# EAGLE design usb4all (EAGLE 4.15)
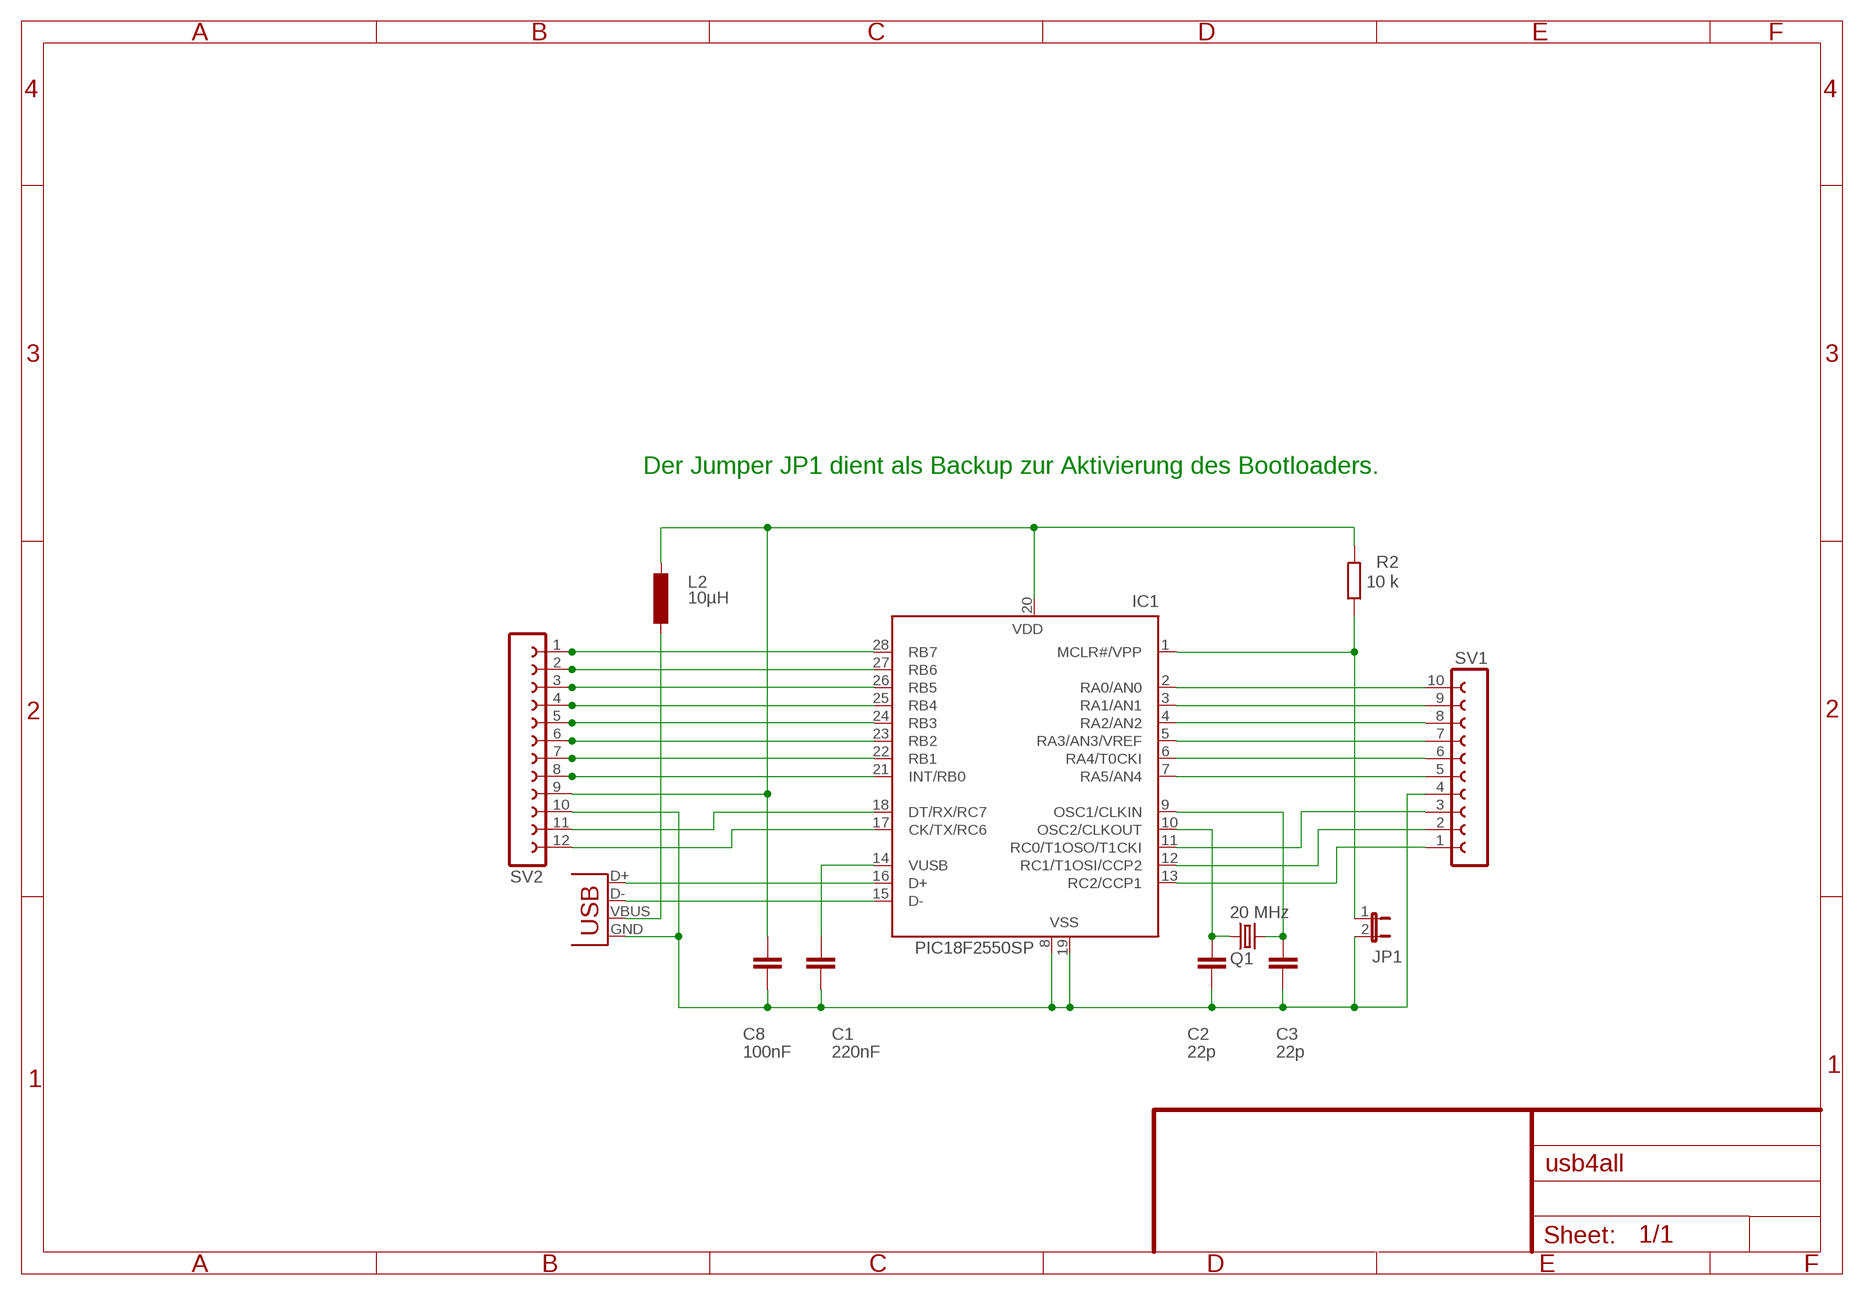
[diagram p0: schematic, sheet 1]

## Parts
C1  220nF  C-EU050-025X075  [C050-025X075]
C2  22p  C-EU025-025X050  [C025-025X050]
C3  22p  C-EU025-025X050  [C025-025X050]
C8  100nF  C-EU050-025X075  [C050-025X075]
IC1  PIC18F2550SP  PIC18F2455SP  [DIL28-3]
JP1  JP1E  [JP1]
L2  10µH  L-EU0207/10  [0207/10]
Q1  20 MHz  CRYTALHC18U-V  [HC18U-V]
R2  10 k  R-EU_0207/10  [0207/10]
SV1  FE10-1  [FE10]
SV2  FE12-1  [FE12]
X2  USB-B-H  [USB-B-H]

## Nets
+5V: C8.1 IC1.20(VDD) L2.2 R2.2 SV2.9
GND: C1.2 C2.2 C3.2 C8.2 IC1.8(VSS) IC1.19(VSS) JP1.2 SV1.4 SV2.10 X2.GND
N$1: IC1.15(D-) X2.D-
N$2: IC1.16(D+) X2.D+
N$3: L2.1 X2.VBUS
N$4: IC1.28(RB7) SV2.1
N$5: C1.1 IC1.14(VUSB)
N$6: C2.1 IC1.10(OSC2/CLKOUT) Q1.1
N$7: C3.1 IC1.9(OSC1/CLKIN) Q1.2
N$8: IC1.1(MCLR#/VPP) JP1.1 R2.1
N$9: IC1.27(RB6) SV2.2
N$10: IC1.26(RB5) SV2.3
N$11: IC1.2(RA0/AN0) SV1.10
N$12: IC1.25(RB4) SV2.4
N$13: IC1.24(RB3) SV2.5
N$14: IC1.23(RB2) SV2.6
N$15: IC1.22(RB1) SV2.7
N$16: IC1.21(INT/RB0) SV2.8
N$17: IC1.18(DT/RX/RC7) SV2.11
N$18: IC1.17(CK/TX/RC6) SV2.12
N$19: IC1.7(RA5/AN4) SV1.5
N$20: IC1.3(RA1/AN1) SV1.9
N$21: IC1.4(RA2/AN2) SV1.8
N$22: IC1.5(RA3/AN3/VREF) SV1.7
N$23: IC1.6(RA4/T0CKI) SV1.6
N$24: IC1.12(RC1/T1OSI/CCP2) SV1.2
N$25: IC1.11(RC0/T1OSO/T1CKI) SV1.3
N$26: IC1.13(RC2/CCP1) SV1.1

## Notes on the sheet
- Der Jumper JP1 dient als Backup zur Aktivierung des Bootloaders.

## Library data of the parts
C1-C3 C8 = rcl:C-EU: CAPACITOR, European symbol
IC1 = sprut:PIC18F2455: FLASH based microcontroler USB 2.0 24K /ROM- 2048 Bytes RAM
JP1 = jumper:JP1E: JUMPER
L2 = rcl:L-EU: INDUCTOR, European symbol
Q1 = crystal:CRYTAL: CRYSTAL
R2 = rcl:R-EU_: RESISTOR, European symbol
SV1 = con-lsta:FE10-1: FEMALE HEADER
SV2 = con-lsta:FE12-1: FEMALE HEADER
X2 = con-usb:USB: USB Connectors

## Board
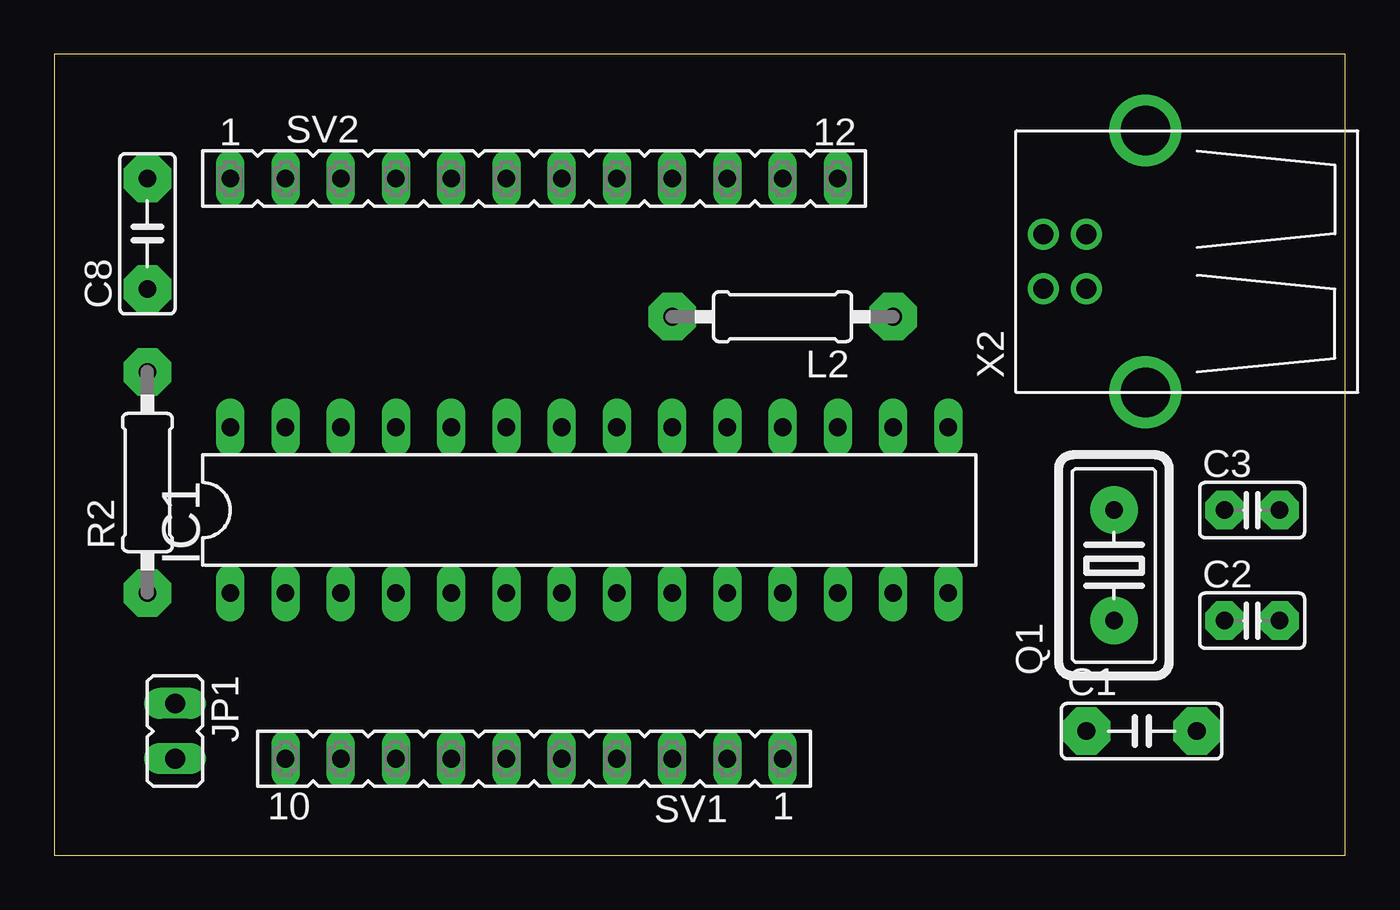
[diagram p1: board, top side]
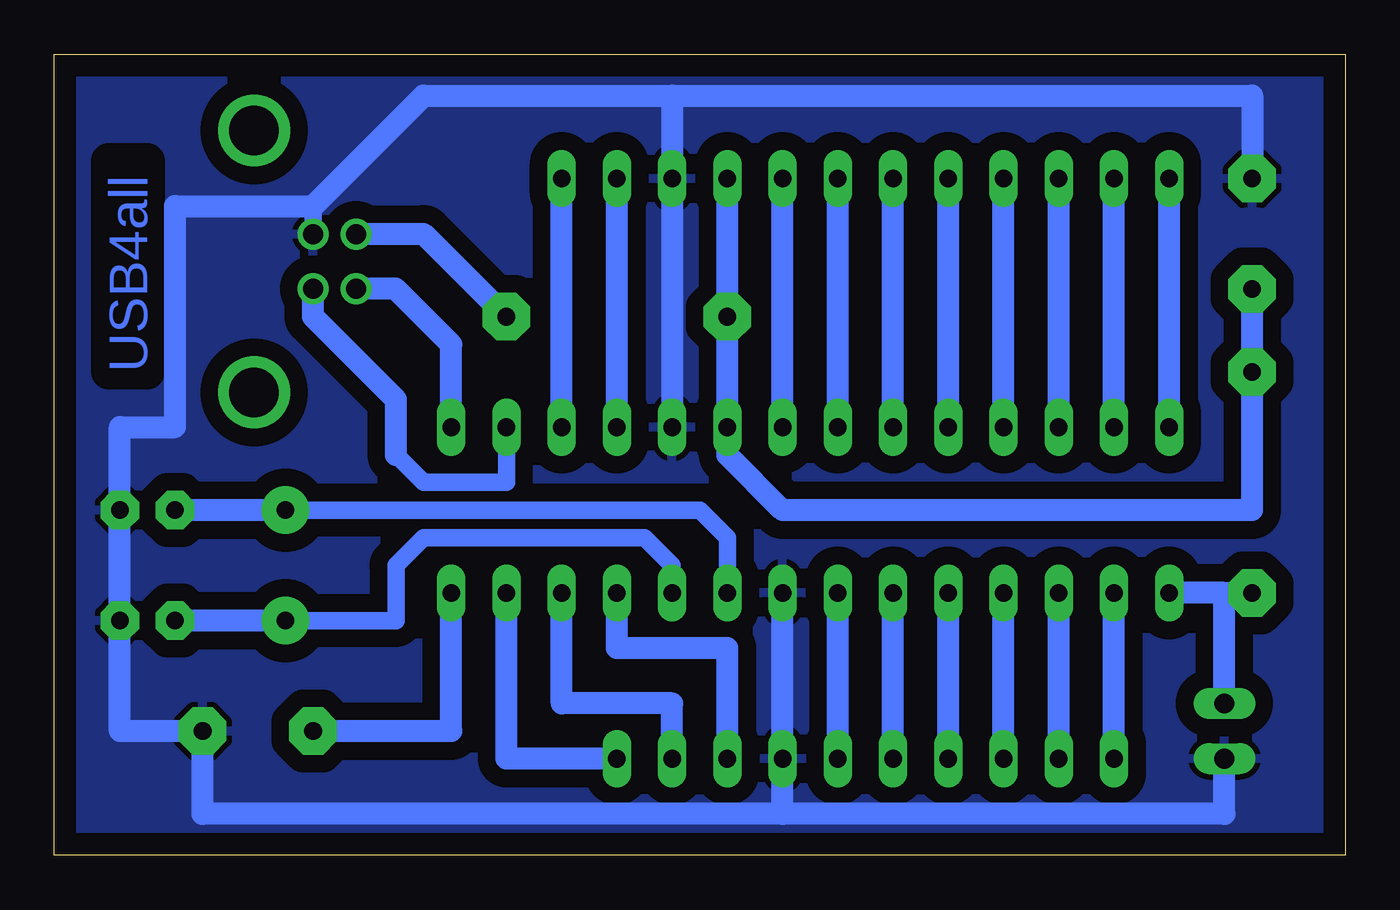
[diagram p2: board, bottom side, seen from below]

Size 59.36 x 36.82 mm. Coordinates in mm from the lower left corner, seen from the top.
Outline: 0,0 59.36,0 59.36,36.82 0,36.82 0,0
Copper layers (1*16): Top 0.035mm / dielectric 1.5mm / Bottom 0.035mm
Design rules "default": minimum track width 10mil, minimum drill 24mil, track to track 8mil, track to pad 8mil, pad to pad 8mil, via to via 8mil, smd to smd 8mil, copper to edge 40mil, drill to drill 8mil, minimum pad ring 10mil, minimum via ring 8mil, stop-mask expansion 4mil, vias tented up to drill 0mil, thermal gap 10mil

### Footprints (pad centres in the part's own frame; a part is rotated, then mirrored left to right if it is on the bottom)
C050-025X075 = drill 0.813 pad 2.184 octagon: 1 -2.54,0; 2 2.54,0
C025-025X050 = drill 0.813 pad 1.778 octagon: 1 -1.27,0; 2 1.27,0
DIL28-3 = drill 0.813 long: 1 -16.51,-3.81; 2 -13.97,-3.81; 3 -11.43,-3.81; 4 -8.89,-3.81; 5 -6.35,-3.81; 6 -3.81,-3.81; 7 -1.27,-3.81; 8 1.27,-3.81; 9 3.81,-3.81; 10 6.35,-3.81; 11 8.89,-3.81; 12 11.43,-3.81; 13 13.97,-3.81; 14 16.51,-3.81; 15 16.51,3.81; 16 13.97,3.81; 17 11.43,3.81; 18 8.89,3.81; 19 6.35,3.81; 20 3.81,3.81; 21 1.27,3.81; 22 -1.27,3.81; 23 -3.81,3.81; 24 -6.35,3.81; 25 -8.89,3.81; 26 -11.43,3.81; 27 -13.97,3.81; 28 -16.51,3.81
JP1 = drill 0.914 long: 1 0,-1.27; 2 0,1.27
0207/10 = drill 0.813 pad 2.184 octagon: 1 -5.08,0; 2 5.08,0
HC18U-V = drill 0.813 pad 2.184 round: 1 -2.54,0; 2 2.54,0
FE10 = drill 0.813 long: 1 -11.43,0; 2 -8.89,0; 3 -6.35,0; 4 -3.81,0; 5 -1.27,0; 6 1.27,0; 7 3.81,0; 8 6.35,0; 9 8.89,0; 10 11.43,0
FE12 = drill 0.813 long: 1 -13.97,0; 2 -11.43,0; 3 -8.89,0; 4 -6.35,0; 5 -3.81,0; 6 -1.27,0; 7 1.27,0; 8 3.81,0; 9 6.35,0; 10 8.89,0; 11 11.43,0; 12 13.97,0
USB-B-H = drill 0.914 round: D+ 0,1.25; D- 1.981,1.25; GND 0,-1.25; VBUS 1.981,-1.25 | drill 2.286 round: P$1 -2.718,-6.02; P$2 -2.718,6.02

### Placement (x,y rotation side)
C1  50,5.71 0 top
C2  55.08,10.79 0 top
C3  55.08,15.87 0 top
C8  4.28,28.57 90 top
IC1  24.6,15.87 0 top
JP1  5.55,5.71 180 top
L2  33.49,24.76 180 top
Q1  48.73,13.33 90 top
R2  4.28,17.14 90 top
SV1  22.06,4.44 180 top
SV2  22.06,31.11 0 top
X2  47.46,27.3 180 top

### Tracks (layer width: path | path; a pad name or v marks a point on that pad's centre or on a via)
+5V
  Bottom 1.016: C8.1 R2.2 4.28,15.87 25.87,15.87 28.41,18.41 IC1.20 L2.2 SV2.9
GND
  Bottom 0.813: 47.46,29.84 X2.GND
  Bottom 1.016: C8.2 4.28,34.92 30.95,34.92 | 30.95,34.92 42.38,34.92 47.46,29.84 53.81,29.84 53.81,19.68 56.35,19.68 C3.2 C2.2 56.35,5.71 C1.2 52.54,1.9 25.87,1.9 | IC1.19 SV2.10 30.95,34.92 | 25.87,1.9 SV1.4 IC1.8 25.87,1.9 | 25.87,1.9 5.55,1.9 JP1.2
  pour Bottom (isolate 0.813): -0.8,37.46 60.16,37.46 60.16,-0.64 -0.8,-0.64
N$1
  Bottom 1.016: IC1.15 41.11,23.49 43.67,26.05 X2.D-
N$2
  Bottom 0.813: IC1.16 38.57,17.14 42.38,17.14 43.65,18.41
  Bottom 1.016: 43.65,18.41 43.65,20.95 47.46,24.76 X2.D+
N$3
  Bottom 0.406: 42.38,28.57 42.4,28.55
  Bottom 1.016: 42.4,28.55 X2.VBUS | L2.1 42.38,28.57
N$4
  Bottom 1.016: IC1.28 SV2.1
N$5
  Bottom 1.016: IC1.14 41.11,5.71 C1.1
N$6
  Bottom 0.813: IC1.10 30.95,13.33 32.22,14.6 42.38,14.6 43.65,13.33 43.65,10.79 Q1.1
  Bottom 1.016: Q1.1 C2.1
N$7
  Bottom 0.813: IC1.9 28.41,14.6 29.68,15.87 Q1.2
  Bottom 1.016: Q1.2 C3.1
N$8
  Bottom 1.016: 5.55,12.06 R2.1 | 5.55,12.06 IC1.1 | JP1.1 5.55,12.06
N$9
  Bottom 1.016: IC1.27 SV2.2
N$10
  Bottom 1.016: IC1.26 SV2.3
N$11
  Bottom 1.016: SV1.10 IC1.2
N$12
  Bottom 1.016: IC1.25 SV2.4
N$13
  Bottom 1.016: IC1.24 SV2.5
N$14
  Bottom 1.016: IC1.23 SV2.6
N$15
  Bottom 1.016: IC1.22 SV2.7
N$16
  Bottom 1.016: IC1.21 SV2.8
N$17
  Bottom 1.016: IC1.18 SV2.11
N$18
  Bottom 1.016: IC1.17 SV2.12
N$19
  Bottom 1.016: SV1.5 IC1.7
N$20
  Bottom 1.016: SV1.9 IC1.3
N$21
  Bottom 1.016: SV1.8 IC1.4
N$22
  Bottom 1.016: SV1.7 IC1.5
N$23
  Bottom 1.016: SV1.6 IC1.6
N$24
  Bottom 1.016: SV1.2 30.95,6.98 36.03,6.98 IC1.12
N$25
  Bottom 1.016: IC1.11 33.49,9.52 28.41,9.52 SV1.3
N$26
  Bottom 1.016: IC1.13 38.57,4.44 SV1.1

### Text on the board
Bottom: USB4all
